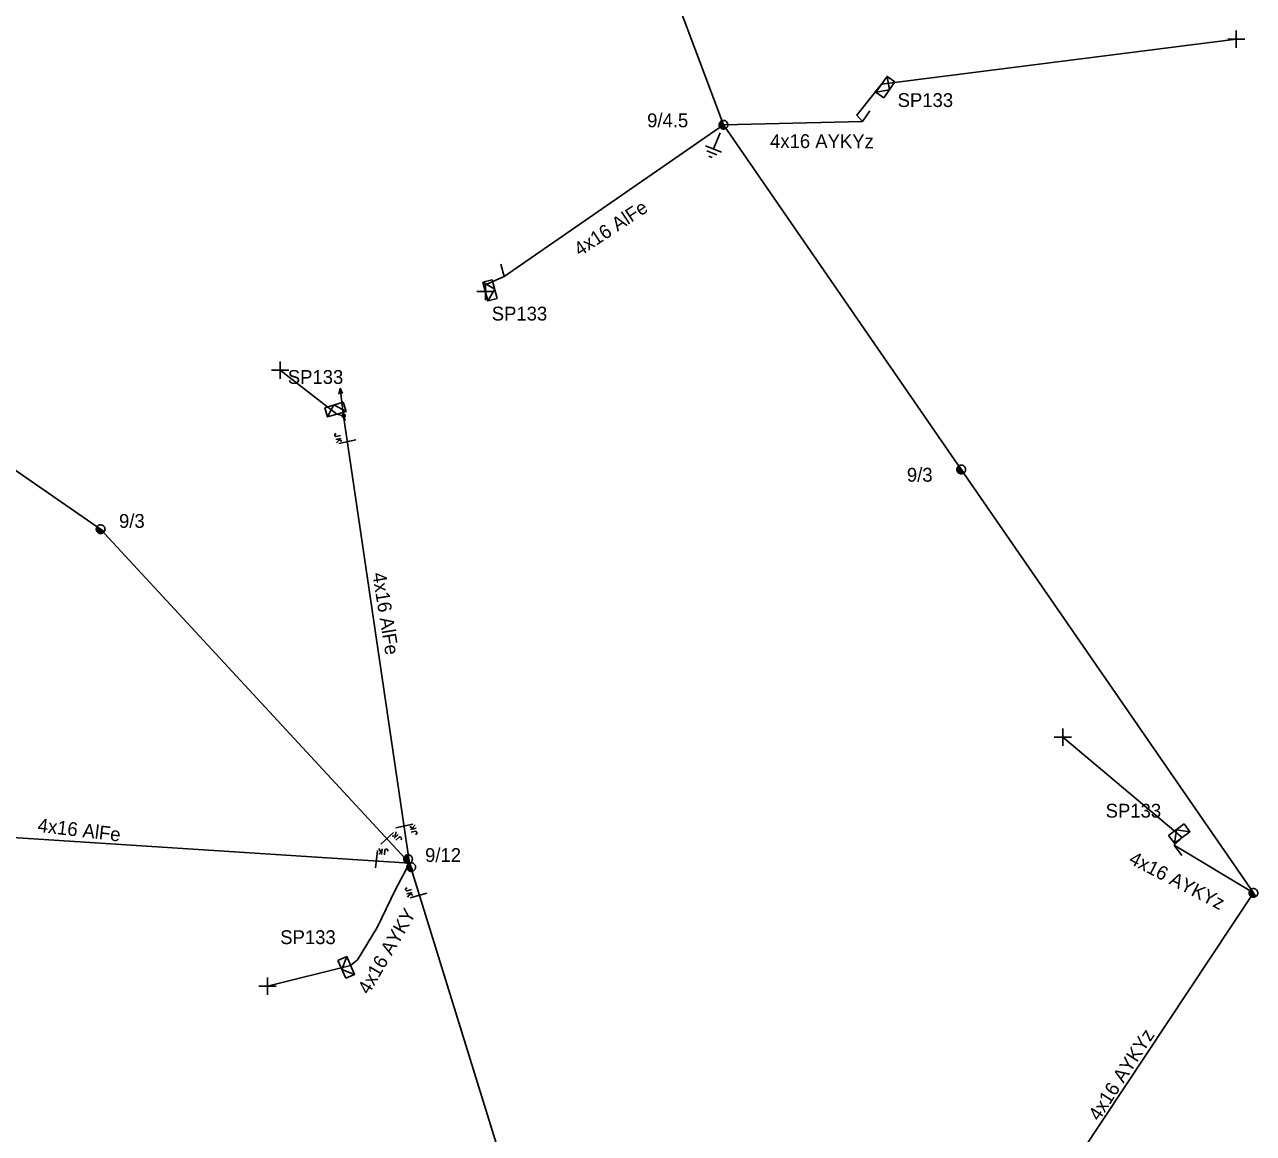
# Model space of a CAD drawing. Extents: x -717562 to -713845, y -1151196 to -1143903.
# Drawn here: x -717170 to -717081, y -1144373.5 to -1144293.2 of the extents above; entities that cross this region are included whole.
import ezdxf

# ---------------------------------------------------------------- set-up
doc = ezdxf.new("R2010")
doc.units = 0
for name, color, linetype in [('Vrstva 1', 7, 'Continuous'), ('Vrstva 12', 7, 'Continuous'), ('Vrstva 13', 7, 'Continuous'), ('Vrstva 14', 7, 'Continuous'), ('Vrstva 15', 7, 'Continuous'), ('Vrstva 18', 7, 'Continuous'), ('Vrstva 2', 7, 'Continuous'), ('Vrstva 31', 7, 'Continuous'), ('Vrstva 33', 7, 'Continuous'), ('Vrstva 34', 7, 'Continuous'), ('Vrstva 4', 7, 'Continuous'), ('Vrstva 52', 7, 'Continuous'), ('Vrstva 53', 7, 'Continuous'), ('Vrstva 54', 7, 'Continuous'), ('Vrstva 55', 7, 'Continuous'), ('Vrstva 59', 7, 'Continuous'), ('Vrstva 9', 7, 'Continuous')]:
    doc.layers.add(name, color=color, linetype=linetype)

# ---------------------------------------------------------------- blocks, each defined once
blk = doc.blocks.new('NN440')
at = {"layer": 'Vrstva 2'}
for points in [[(0.63, 0), (0.63, 0.06), (0.62, 0.13), (0.6, 0.19), (0.58, 0.25), (0.55, 0.31), (0.51, 0.37), (0.47, 0.42), (0.42, 0.46), (0.37, 0.51), (0.32, 0.54), (0.26, 0.57), (0.2, 0.59), (0.13, 0.61), (0.07, 0.62), (0, 0.63), (-0.06, 0.62), (-0.13, 0.61), (-0.19, 0.59), (-0.26, 0.57), (-0.31, 0.54), (-0.37, 0.51), (-0.42, 0.46), (-0.47, 0.42), (-0.51, 0.37), (-0.54, 0.31), (-0.57, 0.25), (-0.6, 0.19), (-0.62, 0.13), (-0.63, 0.06), (-0.63, 0), (-0.63, -0.07), (-0.62, -0.14), (-0.6, -0.2), (-0.57, -0.26), (-0.54, -0.32), (-0.51, -0.37), (-0.47, -0.43), (-0.42, -0.47), (-0.37, -0.51), (-0.31, -0.55), (-0.26, -0.58), (-0.19, -0.6), (-0.13, -0.62), (-0.06, -0.63), (0, -0.63), (0.07, -0.63), (0.13, -0.62), (0.2, -0.6), (0.26, -0.58), (0.32, -0.55), (0.37, -0.51), (0.42, -0.47), (0.47, -0.43), (0.51, -0.37), (0.55, -0.32), (0.58, -0.26), (0.6, -0.2), (0.62, -0.14), (0.63, -0.07), (0.63, 0)], [(-0.63, 0), (0.63, 0)], [(-0.6, -0.18), (0.57, -0.18)], [(-0.51, -0.32), (0.5, -0.32)], [(-0.37, -0.47), (0.35, -0.47)]]:
    blk.add_lwpolyline(points, dxfattribs=at)
blk = doc.blocks.new('NN450')
at = {"layer": 'Vrstva 2'}
for points in [[(0, 0), (0, 0.07), (-0.01, 0.13), (-0.03, 0.19), (-0.05, 0.25), (-0.08, 0.31), (-0.12, 0.37), (-0.16, 0.42), (-0.21, 0.46), (-0.26, 0.51), (-0.31, 0.54), (-0.37, 0.57), (-0.43, 0.59), (-0.5, 0.61), (-0.56, 0.62), (-0.63, 0.62), (-0.69, 0.62), (-0.75, 0.61), (-0.82, 0.59), (-0.88, 0.57), (-0.94, 0.54), (-0.99, 0.51), (-1.04, 0.46), (-1.09, 0.42), (-1.13, 0.37), (-1.17, 0.31), (-1.2, 0.25), (-1.22, 0.19), (-1.24, 0.13), (-1.25, 0.07), (-1.25, 0), (-1.25, -0.07), (-1.24, -0.13), (-1.22, -0.19), (-1.2, -0.25), (-1.17, -0.31), (-1.13, -0.37), (-1.09, -0.42), (-1.04, -0.46), (-0.99, -0.51), (-0.94, -0.54), (-0.88, -0.57), (-0.82, -0.59), (-0.75, -0.61), (-0.69, -0.62), (-0.62, -0.63), (-0.56, -0.62), (-0.5, -0.61), (-0.43, -0.59), (-0.37, -0.57), (-0.31, -0.54), (-0.26, -0.51), (-0.21, -0.46), (-0.16, -0.42), (-0.12, -0.37), (-0.08, -0.31), (-0.05, -0.25), (-0.03, -0.19), (-0.01, -0.13), (0, -0.07), (0, 0)], [(1.25, 0), (1.25, 0.07), (1.24, 0.13), (1.22, 0.19), (1.2, 0.25), (1.17, 0.31), (1.13, 0.37), (1.09, 0.42), (1.04, 0.46), (0.99, 0.51), (0.94, 0.54), (0.88, 0.57), (0.82, 0.59), (0.75, 0.61), (0.69, 0.62), (0.62, 0.62), (0.56, 0.62), (0.5, 0.61), (0.43, 0.59), (0.37, 0.57), (0.31, 0.54), (0.26, 0.51), (0.21, 0.46), (0.16, 0.42), (0.12, 0.37), (0.08, 0.31), (0.05, 0.25), (0.03, 0.19), (0.01, 0.13), (0, 0.07), (0, 0), (0, -0.07), (0.01, -0.13), (0.03, -0.19), (0.05, -0.25), (0.08, -0.31), (0.12, -0.37), (0.16, -0.42), (0.21, -0.46), (0.26, -0.51), (0.31, -0.54), (0.37, -0.57), (0.43, -0.59), (0.5, -0.61), (0.56, -0.62), (0.63, -0.63), (0.69, -0.62), (0.75, -0.61), (0.82, -0.59), (0.88, -0.57), (0.94, -0.54), (0.99, -0.51), (1.04, -0.46), (1.09, -0.42), (1.13, -0.37), (1.17, -0.31), (1.2, -0.25), (1.22, -0.19), (1.24, -0.13), (1.25, -0.07), (1.25, 0)], [(-1.25, 0), (1.25, 0)], [(-1.23, -0.16), (-0.02, -0.16)], [(-1.16, -0.32), (-0.09, -0.32)], [(-1.03, -0.47), (-0.22, -0.47)], [(0.02, -0.16), (1.23, -0.16)], [(0.09, -0.32), (1.16, -0.32)], [(0.22, -0.47), (1.03, -0.47)]]:
    blk.add_lwpolyline(points, dxfattribs=at)
blk = doc.blocks.new('NN560')
at = {"layer": 'Vrstva 2'}
for points in [[(1.999, -0.001), (1.59, 0.141)], [(0, -0.001), (1.999, -0.001)], [(1.999, -0.001), (1.59, -0.134)]]:
    blk.add_lwpolyline(points, dxfattribs=at)
blk = doc.blocks.new('NN840')
at = {"layer": 'Vrstva 15'}
for points in [[(0.003, 0.619), (0.003, -0.631)], [(-0.745, -0.71), (-0.745, -0.66)], [(-0.73, -0.764), (-0.745, -0.71)], [(-0.657, -0.798), (-0.73, -0.764)], [(-0.627, -0.798), (-0.657, -0.798)], [(-0.558, -0.764), (-0.627, -0.798)], [(-0.538, -0.71), (-0.558, -0.764)], [(-0.538, -0.385), (-0.538, -0.71)], [(-0.332, -0.385), (-0.332, -0.798)], [(-0.332, -0.641), (-0.125, -0.385)], [(-0.263, -0.557), (-0.091, -0.798)]]:
    blk.add_lwpolyline(points, dxfattribs=at)
blk = doc.blocks.new('NN800')
at = {"layer": 'Vrstva 1'}
for points in [[(-0.442, 0.442), (0.442, -0.442)], [(-0.442, -0.442), (0.442, 0.442)]]:
    blk.add_lwpolyline(points, dxfattribs=at)
blk = doc.blocks.new('NN630')
at = {"layer": 'Vrstva 9'}
for points in [[(-0.003, -0.7), (-0.703, 0)], [(-0.703, -0.7), (-0.703, 0), (0.697, 0), (0.697, -0.7)], [(-0.703, -0.7), (0.697, -0.7)], [(-0.003, -0.7), (0.697, 0)]]:
    blk.add_lwpolyline(points, dxfattribs=at)
blk = doc.blocks.new('NN810')
at = {"layer": 'Vrstva 14'}
for points in [[(0.004, -0.64), (0.004, -1.89)], [(0.629, -1.89), (-0.621, -1.89)], [(0.388, -2.2), (-0.399, -2.2)], [(0.004, -2.515), (-0.124, -2.515)], [(0.137, -2.515), (0.004, -2.515)]]:
    blk.add_lwpolyline(points, dxfattribs=at)
blk = doc.blocks.new('NN500')
at = {"layer": 'Vrstva 2'}
for points in [[(0, -0.24), (0.02, -0.23), (0.05, -0.23), (0.07, -0.22), (0.09, -0.22), (0.12, -0.2), (0.14, -0.19), (0.16, -0.18), (0.17, -0.16), (0.19, -0.14), (0.2, -0.12), (0.21, -0.1), (0.22, -0.07), (0.23, -0.05), (0.23, -0.02), (0.23, 0), (0.23, 0.02), (0.23, 0.05), (0.22, 0.07), (0.21, 0.1), (0.2, 0.12), (0.19, 0.14), (0.17, 0.16), (0.16, 0.17), (0.14, 0.19), (0.12, 0.2), (0.09, 0.21), (0.07, 0.22), (0.05, 0.23), (0.02, 0.23), (0, 0.23), (-0.03, 0.23), (-0.05, 0.23), (-0.07, 0.22), (-0.1, 0.21), (-0.12, 0.2), (-0.14, 0.19), (-0.16, 0.17), (-0.18, 0.16), (-0.19, 0.14), (-0.2, 0.12), (-0.22, 0.1), (-0.22, 0.07), (-0.23, 0.05), (-0.23, 0.02), (-0.24, 0), (-0.23, -0.02), (-0.23, -0.05), (-0.22, -0.07), (-0.22, -0.1), (-0.2, -0.12), (-0.19, -0.14), (-0.18, -0.16), (-0.16, -0.18), (-0.14, -0.19), (-0.12, -0.2), (-0.1, -0.22), (-0.07, -0.22), (-0.05, -0.23), (-0.03, -0.23), (0, -0.24)], [(0, -0.24), (0.02, -0.23), (0.05, -0.23), (0.07, -0.22), (0.09, -0.22), (0.12, -0.2), (0.14, -0.19), (0.16, -0.18), (0.17, -0.16), (0.19, -0.14), (0.2, -0.12), (0.21, -0.1), (0.22, -0.07), (0.23, -0.05), (0.23, -0.02), (0.23, 0), (0.23, 0.02), (0.23, 0.05), (0.22, 0.07), (0.21, 0.1), (0.2, 0.12), (0.19, 0.14), (0.17, 0.16), (0.16, 0.17), (0.14, 0.19), (0.12, 0.2), (0.09, 0.21), (0.07, 0.22), (0.05, 0.23), (0.02, 0.23), (0, 0.23), (-0.03, 0.23), (-0.05, 0.23), (-0.07, 0.22), (-0.1, 0.21), (-0.12, 0.2), (-0.14, 0.19), (-0.16, 0.17), (-0.18, 0.16), (-0.19, 0.14), (-0.2, 0.12), (-0.22, 0.1), (-0.22, 0.07), (-0.23, 0.05), (-0.23, 0.02), (-0.24, 0), (-0.23, -0.02), (-0.23, -0.05), (-0.22, -0.07), (-0.22, -0.1), (-0.2, -0.12), (-0.19, -0.14), (-0.18, -0.16), (-0.16, -0.18), (-0.14, -0.19), (-0.12, -0.2), (-0.1, -0.22), (-0.07, -0.22), (-0.05, -0.23), (-0.03, -0.23), (0, -0.24)], [(0, -0.21), (0.02, -0.2), (0.04, -0.2), (0.06, -0.2), (0.08, -0.19), (0.1, -0.18), (0.12, -0.17), (0.14, -0.15), (0.15, -0.14), (0.16, -0.12), (0.18, -0.1), (0.19, -0.08), (0.19, -0.06), (0.2, -0.04), (0.2, -0.02), (0.2, 0), (0.2, 0.02), (0.2, 0.04), (0.19, 0.06), (0.19, 0.08), (0.18, 0.1), (0.16, 0.12), (0.15, 0.14), (0.14, 0.15), (0.12, 0.17), (0.1, 0.18), (0.08, 0.19), (0.06, 0.19), (0.04, 0.2), (0.02, 0.2), (0, 0.2), (-0.02, 0.2), (-0.04, 0.2), (-0.06, 0.19), (-0.08, 0.19), (-0.1, 0.18), (-0.12, 0.17), (-0.14, 0.15), (-0.15, 0.14), (-0.17, 0.12), (-0.18, 0.1), (-0.19, 0.08), (-0.2, 0.06), (-0.2, 0.04), (-0.21, 0.02), (-0.21, 0), (-0.21, -0.02), (-0.2, -0.04), (-0.2, -0.06), (-0.19, -0.08), (-0.18, -0.1), (-0.17, -0.12), (-0.15, -0.14), (-0.14, -0.15), (-0.12, -0.17), (-0.1, -0.18), (-0.08, -0.19), (-0.06, -0.2), (-0.04, -0.2), (-0.02, -0.2), (0, -0.21)], [(0, -0.18), (0.02, -0.18), (0.04, -0.17), (0.05, -0.17), (0.07, -0.16), (0.09, -0.15), (0.1, -0.14), (0.12, -0.13), (0.13, -0.12), (0.14, -0.1), (0.15, -0.09), (0.16, -0.07), (0.17, -0.05), (0.17, -0.04), (0.17, -0.02), (0.17, 0), (0.17, 0.02), (0.17, 0.04), (0.17, 0.05), (0.16, 0.07), (0.15, 0.09), (0.14, 0.1), (0.13, 0.12), (0.12, 0.13), (0.1, 0.14), (0.09, 0.15), (0.07, 0.16), (0.05, 0.17), (0.04, 0.17), (0.02, 0.17), (0, 0.18), (-0.02, 0.17), (-0.04, 0.17), (-0.06, 0.17), (-0.07, 0.16), (-0.09, 0.15), (-0.1, 0.14), (-0.12, 0.13), (-0.13, 0.12), (-0.14, 0.1), (-0.15, 0.09), (-0.16, 0.07), (-0.17, 0.05), (-0.17, 0.04), (-0.18, 0.02), (-0.18, 0), (-0.18, -0.02), (-0.17, -0.04), (-0.17, -0.05), (-0.16, -0.07), (-0.15, -0.09), (-0.14, -0.1), (-0.13, -0.12), (-0.12, -0.13), (-0.1, -0.14), (-0.09, -0.15), (-0.07, -0.16), (-0.06, -0.17), (-0.04, -0.17), (-0.02, -0.18), (0, -0.18)], [(0, -0.15), (0.01, -0.15), (0.03, -0.14), (0.04, -0.14), (0.06, -0.13), (0.07, -0.13), (0.08, -0.12), (0.1, -0.11), (0.11, -0.1), (0.12, -0.09), (0.13, -0.07), (0.13, -0.06), (0.14, -0.05), (0.14, -0.03), (0.14, -0.02), (0.14, 0), (0.14, 0.01), (0.14, 0.03), (0.14, 0.04), (0.13, 0.06), (0.13, 0.07), (0.12, 0.09), (0.11, 0.1), (0.1, 0.11), (0.08, 0.12), (0.07, 0.13), (0.06, 0.13), (0.04, 0.14), (0.03, 0.14), (0.01, 0.14), (0, 0.15), (-0.02, 0.14), (-0.03, 0.14), (-0.05, 0.14), (-0.06, 0.13), (-0.07, 0.13), (-0.09, 0.12), (-0.1, 0.11), (-0.11, 0.1), (-0.12, 0.09), (-0.13, 0.07), (-0.13, 0.06), (-0.14, 0.04), (-0.14, 0.03), (-0.15, 0.01), (-0.15, 0), (-0.15, -0.02), (-0.14, -0.03), (-0.14, -0.05), (-0.13, -0.06), (-0.13, -0.07), (-0.12, -0.09), (-0.11, -0.1), (-0.1, -0.11), (-0.09, -0.12), (-0.07, -0.13), (-0.06, -0.13), (-0.05, -0.14), (-0.03, -0.14), (-0.02, -0.15), (0, -0.15)], [(0, -0.12), (0.01, -0.12), (0.02, -0.11), (0.03, -0.11), (0.05, -0.11), (0.06, -0.1), (0.07, -0.09), (0.08, -0.09), (0.09, -0.08), (0.09, -0.07), (0.1, -0.06), (0.11, -0.05), (0.11, -0.04), (0.11, -0.02), (0.11, -0.01), (0.12, 0), (0.11, 0.01), (0.11, 0.02), (0.11, 0.04), (0.11, 0.05), (0.1, 0.06), (0.09, 0.07), (0.09, 0.08), (0.08, 0.09), (0.07, 0.09), (0.06, 0.1), (0.05, 0.11), (0.03, 0.11), (0.02, 0.11), (0.01, 0.12), (0, 0.12), (-0.01, 0.12), (-0.03, 0.11), (-0.04, 0.11), (-0.05, 0.11), (-0.06, 0.1), (-0.07, 0.09), (-0.08, 0.09), (-0.09, 0.08), (-0.1, 0.07), (-0.1, 0.06), (-0.11, 0.05), (-0.11, 0.04), (-0.12, 0.02), (-0.12, 0.01), (-0.12, 0), (-0.12, -0.01), (-0.12, -0.02), (-0.11, -0.04), (-0.11, -0.05), (-0.1, -0.06), (-0.1, -0.07), (-0.09, -0.08), (-0.08, -0.09), (-0.07, -0.09), (-0.06, -0.1), (-0.05, -0.11), (-0.04, -0.11), (-0.03, -0.11), (-0.01, -0.12), (0, -0.12)], [(0, -0.09), (0.01, -0.09), (0.02, -0.09), (0.03, -0.08), (0.03, -0.08), (0.04, -0.08), (0.05, -0.07), (0.06, -0.07), (0.06, -0.06), (0.07, -0.05), (0.07, -0.04), (0.08, -0.04), (0.08, -0.03), (0.08, -0.02), (0.09, -0.01), (0.09, 0), (0.09, 0.01), (0.08, 0.02), (0.08, 0.03), (0.08, 0.03), (0.07, 0.04), (0.07, 0.05), (0.06, 0.06), (0.06, 0.06), (0.05, 0.07), (0.04, 0.07), (0.03, 0.08), (0.03, 0.08), (0.02, 0.08), (0.01, 0.09), (0, 0.09), (-0.01, 0.09), (-0.02, 0.08), (-0.03, 0.08), (-0.04, 0.08), (-0.04, 0.07), (-0.05, 0.07), (-0.06, 0.06), (-0.07, 0.06), (-0.07, 0.05), (-0.08, 0.04), (-0.08, 0.03), (-0.08, 0.03), (-0.09, 0.02), (-0.09, 0.01), (-0.09, 0), (-0.09, -0.01), (-0.09, -0.02), (-0.08, -0.03), (-0.08, -0.04), (-0.08, -0.04), (-0.07, -0.05), (-0.07, -0.06), (-0.06, -0.07), (-0.05, -0.07), (-0.04, -0.08), (-0.04, -0.08), (-0.03, -0.08), (-0.02, -0.09), (-0.01, -0.09), (0, -0.09)], [(0, -0.06), (0, -0.06), (0.01, -0.06), (0.02, -0.05), (0.02, -0.05), (0.03, -0.05), (0.03, -0.05), (0.04, -0.04), (0.04, -0.04), (0.05, -0.03), (0.05, -0.03), (0.05, -0.02), (0.05, -0.02), (0.05, -0.01), (0.06, -0.01), (0.06, 0), (0.06, 0.01), (0.05, 0.01), (0.05, 0.02), (0.05, 0.02), (0.05, 0.03), (0.05, 0.03), (0.04, 0.04), (0.04, 0.04), (0.03, 0.05), (0.03, 0.05), (0.02, 0.05), (0.02, 0.05), (0.01, 0.06), (0, 0.06), (0, 0.06), (-0.01, 0.06), (-0.01, 0.06), (-0.02, 0.05), (-0.02, 0.05), (-0.03, 0.05), (-0.03, 0.05), (-0.04, 0.04), (-0.04, 0.04), (-0.05, 0.03), (-0.05, 0.03), (-0.05, 0.02), (-0.06, 0.02), (-0.06, 0.01), (-0.06, 0.01), (-0.06, 0), (-0.06, -0.01), (-0.06, -0.01), (-0.06, -0.02), (-0.05, -0.02), (-0.05, -0.03), (-0.05, -0.03), (-0.04, -0.04), (-0.04, -0.04), (-0.03, -0.05), (-0.03, -0.05), (-0.02, -0.05), (-0.02, -0.05), (-0.01, -0.06), (-0.01, -0.06), (0, -0.06)], [(0, -0.03), (0, -0.03), (0, -0.03), (0.01, -0.03), (0.01, -0.03), (0.01, -0.02), (0.02, -0.02), (0.02, -0.02), (0.02, -0.02), (0.02, -0.02), (0.02, -0.01), (0.02, -0.01), (0.03, -0.01), (0.03, -0.01), (0.03, 0), (0.03, 0), (0.03, 0), (0.03, 0.01), (0.03, 0.01), (0.02, 0.01), (0.02, 0.01), (0.02, 0.02), (0.02, 0.02), (0.02, 0.02), (0.02, 0.02), (0.01, 0.02), (0.01, 0.02), (0.01, 0.03), (0, 0.03), (0, 0.03), (0, 0.03), (0, 0.03), (-0.01, 0.03), (-0.01, 0.03), (-0.01, 0.02), (-0.02, 0.02), (-0.02, 0.02), (-0.02, 0.02), (-0.02, 0.02), (-0.02, 0.02), (-0.03, 0.01), (-0.03, 0.01), (-0.03, 0.01), (-0.03, 0.01), (-0.03, 0), (-0.03, 0), (-0.03, 0), (-0.03, -0.01), (-0.03, -0.01), (-0.03, -0.01), (-0.03, -0.01), (-0.02, -0.02), (-0.02, -0.02), (-0.02, -0.02), (-0.02, -0.02), (-0.02, -0.02), (-0.01, -0.03), (-0.01, -0.03), (-0.01, -0.03), (0, -0.03), (0, -0.03)], [(0.23, 0), (0.7, 0)]]:
    blk.add_lwpolyline(points, dxfattribs=at)
blk = doc.blocks.new('NN510')
at = {"layer": 'Vrstva 2'}
blk.add_lwpolyline([(0.001, 0.002), (0.001, 0.939)], dxfattribs=at)

msp = doc.modelspace()

# ---------------------------------------------------------------- linework, layer by layer
at = {"layer": 'Vrstva 1'}
for points in [[(-717137.446, -1144243.439), (-717129.597, -1144273.23), (-717119.356, -1144300.489), (-717102.146, -1144325.429), (-717080.996, -1144356.058)], [(-717142.076, -1144353.909), (-717164.446, -1144329.749), (-717194.356, -1144309.079), (-717215.256, -1144287.869), (-717232.506, -1144259.719)], [(-717063.536, -1144519.499), (-717088.976, -1144491.919), (-717104.646, -1144465.559), (-717112.106, -1144434.029), (-717129.316, -1144395.139), (-717142.076, -1144353.909)]]:
    msp.add_lwpolyline(points, dxfattribs=at)
at = {"layer": 'Vrstva 4'}
for points in [[(-717119.356, -1144300.489), (-717135.226, -1144311.469), (-717136.716, -1144312.119), (-717136.596, -1144312.559)], [(-717142.076, -1144353.909), (-717146.856, -1144321.538), (-717147.356, -1144321.429)], [(-717142.077, -1144353.909), (-717171.546, -1144352.009), (-717198.446, -1144350.139), (-717198.576, -1144350.409)]]:
    msp.add_lwpolyline(points, dxfattribs=at)
at = {"layer": 'Vrstva 52'}
for points in [[(-717142.077, -1144353.909), (-717143.096, -1144355.819), (-717144.416, -1144358.569), (-717145.856, -1144360.899), (-717146.346, -1144361.319)], [(-717080.996, -1144356.058), (-717095.016, -1144377.189), (-717095.524, -1144377.548)]]:
    msp.add_lwpolyline(points, dxfattribs=at)
at = {"layer": 'Vrstva 54'}
for points in [[(-717119.356, -1144300.489), (-717109.306, -1144300.249), (-717109.706, -1144299.799), (-717107.916, -1144297.559)], [(-717080.996, -1144356.058), (-717086.726, -1144352.609), (-717086.156, -1144352.059)]]:
    msp.add_lwpolyline(points, dxfattribs=at)
at = {"layer": 'Vrstva 59'}
for points in [[(-717107.917, -1144297.559), (-717082.235, -1144294.302)], [(-717147.356, -1144321.429), (-717151.44, -1144318.25)], [(-717086.156, -1144352.059), (-717094.794, -1144344.788)], [(-717146.347, -1144361.319), (-717152.373, -1144362.815)]]:
    msp.add_lwpolyline(points, dxfattribs=at)

# ---------------------------------------------------------------- block references
at = {"layer": 'Vrstva 13'}
for name, p, rotation in [('NN510', (-717109.306, -1144300.249), -34.59962222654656), ('NN510', (-717135.226, -1144311.469), 15.344449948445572), ('NN560', (-717146.856, -1144321.538), 97.48067146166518), ('NN510', (-717086.726, -1144352.609), -143.7430249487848)]:
    msp.add_blockref(name, p, dxfattribs=dict(at, rotation=rotation))
for name, p, xscale, yscale, rotation in [('NN440', (-717119.356, -1144300.489), 0.5, 0.5, -67.79625838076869), ('NN500', (-717146.856, -1144321.539), 0.5, 0.5000000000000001, -73.23600008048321), ('NN440', (-717102.146, -1144325.429), 0.5, 0.5, -53.90663609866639), ('NN440', (-717164.446, -1144329.749), 0.49999999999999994, 0.49999999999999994, -33.920650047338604), ('NN450', (-717142.076, -1144353.909), 0.5000000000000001, 0.5, -68.37483337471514), ('NN440', (-717080.996, -1144356.059), 0.5, 0.5, -53.90663601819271)]:
    msp.add_blockref(name, p, dxfattribs=dict(at, xscale=xscale, yscale=yscale, rotation=rotation))
at = {"layer": 'Vrstva 15', "rotation": -22.351994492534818}
msp.add_blockref('NN810', (-717119.356, -1144300.49), dxfattribs=at)
at = {"layer": 'Vrstva 18'}
for p, rotation in [((-717146.579, -1144323.417), -77.37131110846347), ((-717142.467, -1144351.234), 102.62868889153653), ((-717143.712, -1144352.123), 132.4798221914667), ((-717144.482, -1144353.625), 173.270211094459), ((-717141.43, -1144356.243), -74.4836999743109)]:
    msp.add_blockref('NN840', p, dxfattribs=dict(at, rotation=rotation))
at = {"layer": 'Vrstva 31'}
for p, rotation in [((-717107.916, -1144297.559), 54.71598333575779), ((-717136.596, -1144312.559), 104.68883891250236), ((-717147.356, -1144321.429), -163.2357806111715), ((-717086.156, -1144352.059), -143.7430249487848), ((-717146.346, -1144361.319), -66.25876659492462)]:
    msp.add_blockref('NN630', p, dxfattribs=dict(at, rotation=rotation))
at = {"layer": 'Vrstva 34'}
for p, rotation in [((-717082.235, -1144294.302), 45), ((-717136.596, -1144312.559), 45.000000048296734), ((-717151.44, -1144318.25), 44.99999995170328), ((-717094.794, -1144344.788), 45), ((-717152.373, -1144362.815), 45)]:
    msp.add_blockref('NN800', p, dxfattribs=dict(at, rotation=rotation))

# ---------------------------------------------------------------- texts
at = {"layer": 'Vrstva 12'}
for s, p in [('9/4.5', (-717124.884, -1144300.67)), ('9/3', (-717106.081, -1144326.314)), ('9/3', (-717163.115, -1144329.653)), ('9/12', (-717140.959, -1144353.828))]:
    msp.add_text(s, height=1, dxfattribs=at).set_placement(p)
at = {"layer": 'Vrstva 33'}
for p in [(-717106.752, -1144299.205), (-717136.133, -1144314.651), (-717150.897, -1144319.238), (-717091.691, -1144350.62), (-717151.443, -1144359.77)]:
    msp.add_text('SP133', height=1, dxfattribs=at).set_placement(p)
at = {"layer": 'Vrstva 53'}
for s, rotation, p in [('4x16 AlFe', 33.471, (-717129.759, -1144310.037)), ('4x16 AlFe', 279.252, (-717144.784, -1144332.962)), ('4x16 AlFe', 353.271, (-717169.041, -1144351.646)), ('4x16 AYKYz', 57.214, (-717092.172, -1144372.631))]:
    msp.add_text(s, height=1, rotation=rotation, dxfattribs=at).set_placement(p)
at = {"layer": 'Vrstva 54'}
msp.add_text('4x16 AYKY', height=1, rotation=59.76, dxfattribs=at).set_placement((-717145.033, -1144363.479))
at = {"layer": 'Vrstva 55'}
for rotation, p in [(359.86, (-717115.986, -1144302.169)), (332.756, (-717090.081, -1144353.894))]:
    msp.add_text('4x16 AYKYz', height=1, rotation=rotation, dxfattribs=at).set_placement(p)

doc.saveas('drawing.dxf')
